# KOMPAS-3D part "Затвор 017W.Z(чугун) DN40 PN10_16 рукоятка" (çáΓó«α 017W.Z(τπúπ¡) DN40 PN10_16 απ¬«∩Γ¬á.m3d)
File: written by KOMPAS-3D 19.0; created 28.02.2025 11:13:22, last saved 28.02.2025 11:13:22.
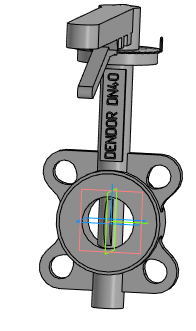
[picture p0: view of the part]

Document properties: Автор: Евгений; Полное имя файла: Затвор 017W.Z(чугун) DN40 PN10_16 рукоятка.a3d

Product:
- Part/product: Затвор 017W.Z(чугун) DN40 PN10_16 рукоятка
    Масса: 3.51666

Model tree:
1. Операция без истории:1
